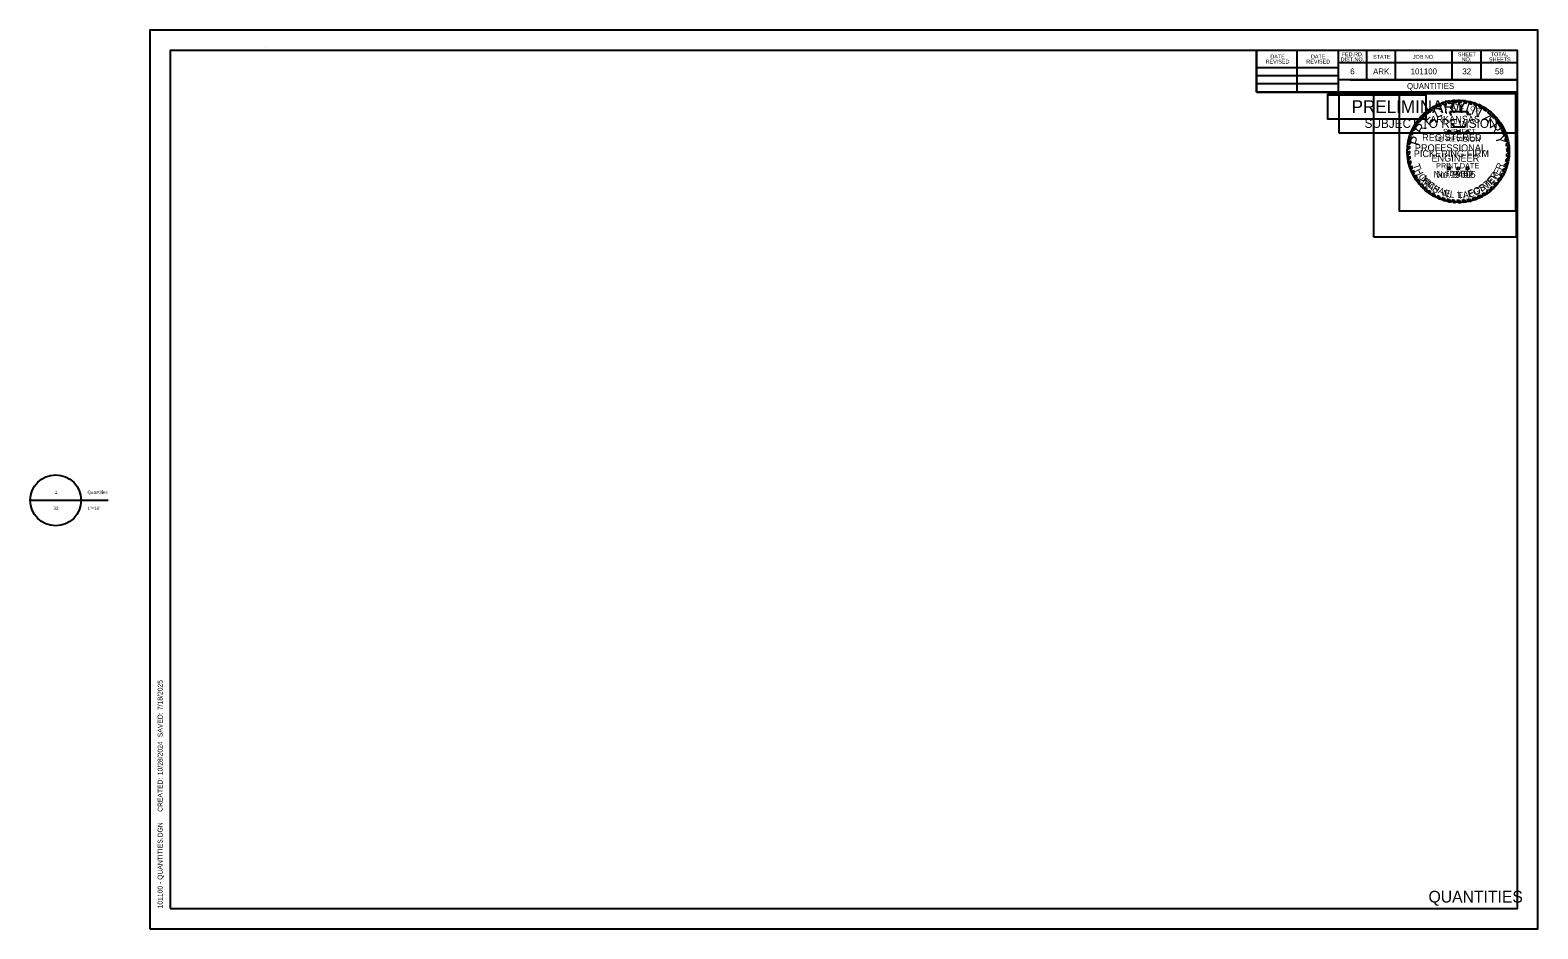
# Model space of a CAD drawing. Extents: x -0.12 to 1.42, y 0 to 0.92.
import ezdxf

# ---------------------------------------------------------------- set-up
doc = ezdxf.new("R2010")
doc.units = 0
for name, color, linetype in [('Default', 7, 'Continuous'), ('DSN_DRFT_Guideline-No-Plot', 7, 'Continuous'), ('SHET_Annotations', 7, 'Continuous'), ('SHET_Border-Lines', 7, 'Continuous'), ('SHET_Border-Text', 7, 'Continuous'), ('SHET_Stamp-Prelim', 7, 'Continuous'), ('SHET_Stamp-Seal', 7, 'Continuous'), ('STAMP_PE DIG SIG', 7, 'Continuous'), ('STAMP_PE_BACKGROUND', 7, 'Continuous'), ('STAMP_PE_FOSTER', 7, 'Continuous'), ('STAMP_PE_SEAL-INFO', 7, 'Continuous'), ('STAMP_PE_TAEGTMEYER', 7, 'Continuous'), ('STAMP_PRELIMINARY', 7, 'Continuous')]:
    doc.layers.add(name, color=color, linetype=linetype)

msp = doc.modelspace()

# ---------------------------------------------------------------- linework, layer by layer
at = {"layer": 'Default'}
for p, q in [((-0.1223, 0.4371), (-0.0702, 0.4371)), ((-0.096, 0.4371), (-0.0428, 0.4371))]:
    msp.add_line(p, q, dxfattribs=at)
msp.add_circle((-0.0962, 0.4371), 0.026, dxfattribs=at)
at = {"layer": 'DSN_DRFT_Guideline-No-Plot'}
msp.add_lwpolyline([(0, 0), (1.4167, 0), (1.4167, 0.9167), (0, 0.9167)], close=True, dxfattribs=at)
at = {"layer": 'SHET_Border-Lines'}
for p, q in [((0.1176, 0.8988), (0.1176, 0.8988)), ((0.1176, 0.8988), (0.1176, 0.8988)), ((1.1296, 0.8534), (1.1296, 0.8958)), ((1.1711, 0.8534), (1.1711, 0.8958)), ((1.2127, 0.8958), (1.2127, 0.8534)), ((1.2417, 0.8958), (1.2417, 0.866)), ((1.2712, 0.8958), (1.2712, 0.866)), ((1.3289, 0.8958), (1.3289, 0.866)), ((1.3584, 0.8958), (1.3584, 0.866)), ((1.1296, 0.8786), (1.2127, 0.8786)), ((1.3958, 0.8832), (1.2127, 0.8832)), ((1.3958, 0.8833), (1.3958, 0.8833)), ((1.1296, 0.8706), (1.2127, 0.8706)), ((1.1296, 0.8622), (1.2127, 0.8622)), ((1.3958, 0.866), (1.2127, 0.866)), ((1.2252, 0.866), (1.3958, 0.866)), ((1.3958, 0.8534), (1.1296, 0.8534))]:
    msp.add_line(p, q, dxfattribs=at)
for points in [[(0.0208, 0.0208), (1.3958, 0.0208), (1.3958, 0.8958), (0.0208, 0.8958)], [(1.1296, 0.8534), (1.3958, 0.8534), (1.3958, 0.8958), (1.1296, 0.8958)]]:
    msp.add_lwpolyline(points, close=True, dxfattribs=at)
at = {"layer": 'SHET_Stamp-Prelim'}
msp.add_lwpolyline([(1.2137, 0.8119), (1.3948, 0.8119), (1.3948, 0.8524), (1.2137, 0.8524)], close=True, dxfattribs=at)
at = {"layer": 'SHET_Stamp-Seal'}
msp.add_line((1.3219, 0.7895), (1.3219, 0.7895), dxfattribs=at)
msp.add_lwpolyline([(1.249, 0.7057), (1.3948, 0.7057), (1.3948, 0.8524), (1.249, 0.8524)], close=True, dxfattribs=at)
at = {"layer": 'STAMP_PE DIG SIG'}
msp.add_lwpolyline([(1.2022, 0.8508), (1.3022, 0.8508), (1.3022, 0.8258), (1.2022, 0.8258)], close=True, dxfattribs=at)
at = {"layer": 'STAMP_PE_BACKGROUND'}
for points in [[(1.2022, 0.8517), (1.3022, 0.8517), (1.3022, 0.8258), (1.2022, 0.8258)], [(1.3942, 0.8517), (1.275, 0.8517), (1.275, 0.7325), (1.3942, 0.7325)]]:
    msp.add_lwpolyline(points, close=True, dxfattribs=at)
at = {"layer": 'STAMP_PE_SEAL-INFO'}
for p, q in [((1.3002, 0.8313), (1.3028, 0.8306)), ((1.3021, 0.833), (1.3051, 0.8325)), ((1.3042, 0.8348), (1.3068, 0.8337)), ((1.3066, 0.8363), (1.309, 0.8352)), ((1.3087, 0.8377), (1.3112, 0.8365)), ((1.3112, 0.8391), (1.3138, 0.8378)), ((1.3137, 0.8403), (1.3158, 0.8387)), ((1.3165, 0.8415), (1.3181, 0.8397)), ((1.3184, 0.8422), (1.3206, 0.8405)), ((1.3217, 0.8432), (1.3233, 0.8413)), ((1.3239, 0.8438), (1.3259, 0.8418)), ((1.3266, 0.8443), (1.3283, 0.8422)), ((1.3269, 0.8337), (1.3456, 0.8337)), ((1.3276, 0.832), (1.3269, 0.8337)), ((1.3281, 0.8303), (1.3276, 0.832)), ((1.3295, 0.8447), (1.331, 0.8426)), ((1.3336, 0.8427), (1.3318, 0.8449)), ((1.3364, 0.8428), (1.3348, 0.845)), ((1.3389, 0.8426), (1.3375, 0.845)), ((1.3417, 0.8424), (1.3401, 0.8448)), ((1.3441, 0.842), (1.3427, 0.8445)), ((1.3456, 0.8337), (1.3443, 0.831)), ((1.3473, 0.8413), (1.3463, 0.8439)), ((1.3495, 0.8407), (1.3486, 0.8433)), ((1.352, 0.8399), (1.3512, 0.8426)), ((1.3544, 0.839), (1.3536, 0.8418)), ((1.357, 0.8379), (1.3564, 0.8406)), ((1.3594, 0.8366), (1.359, 0.8394)), ((1.3616, 0.8353), (1.3614, 0.8381)), ((1.364, 0.8337), (1.3639, 0.8366)), ((1.366, 0.8322), (1.3662, 0.8349)), ((1.3685, 0.8301), (1.3687, 0.8331)), ((1.3703, 0.8285), (1.3707, 0.8313)), ((1.2891, 0.8167), (1.2918, 0.8171)), ((1.2904, 0.8191), (1.2931, 0.8192)), ((1.2917, 0.8213), (1.2946, 0.8215)), ((1.293, 0.8232), (1.2959, 0.8232)), ((1.2946, 0.8253), (1.2977, 0.8254)), ((1.2965, 0.8276), (1.2994, 0.8274)), ((1.2983, 0.8295), (1.3014, 0.8293)), ((1.3282, 0.8297), (1.3281, 0.8303)), ((1.3293, 0.8201), (1.3291, 0.8213)), ((1.331, 0.8201), (1.3293, 0.8201)), ((1.331, 0.8177), (1.331, 0.8201)), ((1.3423, 0.8177), (1.331, 0.8177)), ((1.3424, 0.8196), (1.3423, 0.8177)), ((1.3429, 0.8213), (1.3424, 0.8196)), ((1.3443, 0.831), (1.3478, 0.831)), ((1.3478, 0.831), (1.347, 0.8297)), ((1.3723, 0.8264), (1.3727, 0.8294)), ((1.3738, 0.8247), (1.3746, 0.8273)), ((1.3756, 0.8223), (1.3764, 0.8251)), ((1.3769, 0.8206), (1.3779, 0.8232)), ((1.3786, 0.8178), (1.3796, 0.8205)), ((1.3797, 0.8157), (1.381, 0.8182)), ((1.381, 0.813), (1.3823, 0.8157)), ((1.2862, 0.8008), (1.2838, 0.7996)), ((1.2867, 0.8034), (1.2841, 0.802)), ((1.2847, 0.8048), (1.2873, 0.8059)), ((1.2853, 0.8071), (1.2879, 0.808)), ((1.2862, 0.8099), (1.2889, 0.8106)), ((1.287, 0.8121), (1.2898, 0.8129)), ((1.288, 0.8145), (1.2908, 0.8151)), ((1.3252, 0.8129), (1.3241, 0.8137)), ((1.3241, 0.8137), (1.3255, 0.8137)), ((1.3248, 0.8116), (1.3252, 0.8129)), ((1.3259, 0.8124), (1.3248, 0.8116)), ((1.3255, 0.8137), (1.3259, 0.815)), ((1.3259, 0.815), (1.3264, 0.8137)), ((1.327, 0.8116), (1.3259, 0.8124)), ((1.3264, 0.8137), (1.3277, 0.8137)), ((1.3277, 0.8137), (1.3266, 0.8129)), ((1.3266, 0.8129), (1.327, 0.8116)), ((1.3347, 0.8129), (1.3336, 0.8137)), ((1.3336, 0.8137), (1.335, 0.8137)), ((1.3343, 0.8116), (1.3347, 0.8129)), ((1.3354, 0.8124), (1.3343, 0.8116)), ((1.335, 0.8137), (1.3354, 0.815)), ((1.3354, 0.815), (1.3358, 0.8137)), ((1.3365, 0.8116), (1.3354, 0.8124)), ((1.3358, 0.8137), (1.3372, 0.8137)), ((1.3372, 0.8137), (1.3361, 0.8129)), ((1.3361, 0.8129), (1.3365, 0.8116)), ((1.3442, 0.8129), (1.3431, 0.8137)), ((1.3431, 0.8137), (1.3445, 0.8137)), ((1.3438, 0.8116), (1.3442, 0.8129)), ((1.3449, 0.8124), (1.3438, 0.8116)), ((1.3445, 0.8137), (1.3449, 0.815)), ((1.3449, 0.815), (1.3453, 0.8137)), ((1.346, 0.8116), (1.3449, 0.8124)), ((1.3453, 0.8137), (1.3467, 0.8137)), ((1.3467, 0.8137), (1.3456, 0.8129)), ((1.3456, 0.8129), (1.346, 0.8116)), ((1.3818, 0.8112), (1.3832, 0.8136)), ((1.3829, 0.8081), (1.3844, 0.8107)), ((1.3835, 0.8061), (1.3851, 0.8086)), ((1.3842, 0.8029), (1.386, 0.8054)), ((1.3846, 0.8008), (1.3866, 0.8028)), ((1.2857, 0.796), (1.2834, 0.7946)), ((1.2856, 0.7933), (1.2834, 0.7914)), ((1.2859, 0.7984), (1.2835, 0.7968)), ((1.2857, 0.791), (1.2835, 0.7892)), ((1.2858, 0.7882), (1.2838, 0.7862)), ((1.2861, 0.7858), (1.2842, 0.7837)), ((1.3846, 0.7855), (1.3871, 0.7867)), ((1.3849, 0.7876), (1.3874, 0.7891)), ((1.385, 0.798), (1.387, 0.7998)), ((1.3851, 0.7956), (1.3873, 0.7973)), ((1.3852, 0.7927), (1.3875, 0.7945)), ((1.3852, 0.7905), (1.3875, 0.792)), ((1.2866, 0.7833), (1.2847, 0.7812)), ((1.2871, 0.7809), (1.2854, 0.7786)), ((1.2878, 0.7784), (1.2861, 0.7761)), ((1.2886, 0.7761), (1.287, 0.7738)), ((1.2895, 0.7737), (1.288, 0.7713)), ((1.2905, 0.7715), (1.2892, 0.769)), ((1.3252, 0.7754), (1.3241, 0.7763)), ((1.3241, 0.7763), (1.3255, 0.7763)), ((1.3248, 0.7741), (1.3252, 0.7754)), ((1.3259, 0.7749), (1.3248, 0.7741)), ((1.3255, 0.7763), (1.3259, 0.7776)), ((1.3259, 0.7776), (1.3264, 0.7763)), ((1.327, 0.7741), (1.3259, 0.7749)), ((1.3264, 0.7763), (1.3277, 0.7763)), ((1.3277, 0.7763), (1.3266, 0.7754)), ((1.3266, 0.7754), (1.327, 0.7741)), ((1.3347, 0.7754), (1.3336, 0.7763)), ((1.3336, 0.7763), (1.335, 0.7763)), ((1.3343, 0.7741), (1.3347, 0.7754)), ((1.3354, 0.7749), (1.3343, 0.7741)), ((1.335, 0.7763), (1.3354, 0.7776)), ((1.3354, 0.7776), (1.3358, 0.7763)), ((1.3365, 0.7741), (1.3354, 0.7749)), ((1.3358, 0.7763), (1.3372, 0.7763)), ((1.3372, 0.7763), (1.3361, 0.7754)), ((1.3361, 0.7754), (1.3365, 0.7741)), ((1.3442, 0.7754), (1.3431, 0.7763)), ((1.3431, 0.7763), (1.3445, 0.7763)), ((1.3438, 0.7741), (1.3442, 0.7754)), ((1.3449, 0.7749), (1.3438, 0.7741)), ((1.3445, 0.7763), (1.3449, 0.7776)), ((1.3449, 0.7776), (1.3453, 0.7763)), ((1.346, 0.7741), (1.3449, 0.7749)), ((1.3453, 0.7763), (1.3467, 0.7763)), ((1.3467, 0.7763), (1.3456, 0.7754)), ((1.3456, 0.7754), (1.346, 0.7741)), ((1.3799, 0.7705), (1.3826, 0.7709)), ((1.3808, 0.7724), (1.3835, 0.7729)), ((1.382, 0.7753), (1.3847, 0.776)), ((1.3827, 0.7774), (1.3855, 0.7785)), ((1.3835, 0.7802), (1.3862, 0.7813)), ((1.3841, 0.7827), (1.3867, 0.7838)), ((1.2918, 0.769), (1.2907, 0.7662)), ((1.2931, 0.7667), (1.2921, 0.7641)), ((1.2942, 0.765), (1.2936, 0.7619)), ((1.2958, 0.7628), (1.2952, 0.7598)), ((1.2975, 0.7607), (1.297, 0.7578)), ((1.2992, 0.7588), (1.2988, 0.7559)), ((1.301, 0.757), (1.3008, 0.754)), ((1.3029, 0.7552), (1.3029, 0.7523)), ((1.3679, 0.7553), (1.3706, 0.7545)), ((1.3702, 0.7573), (1.3727, 0.7566)), ((1.3716, 0.7588), (1.3743, 0.7583)), ((1.3738, 0.7612), (1.3763, 0.7608)), ((1.3755, 0.7634), (1.3783, 0.7634)), ((1.3774, 0.7662), (1.3801, 0.7661)), ((1.3783, 0.7677), (1.3811, 0.768)), ((1.3049, 0.7536), (1.305, 0.7507)), ((1.3068, 0.7522), (1.307, 0.7493)), ((1.3092, 0.7506), (1.3095, 0.7478)), ((1.3111, 0.7495), (1.3117, 0.7466)), ((1.3138, 0.7481), (1.3147, 0.7452)), ((1.3159, 0.7471), (1.3169, 0.7443)), ((1.3187, 0.7461), (1.3198, 0.7433)), ((1.321, 0.7453), (1.3222, 0.7426)), ((1.3238, 0.7445), (1.325, 0.7419)), ((1.326, 0.7441), (1.3274, 0.7415)), ((1.3288, 0.7436), (1.3302, 0.7411)), ((1.3313, 0.7433), (1.3328, 0.7409)), ((1.334, 0.7432), (1.3356, 0.7409)), ((1.3365, 0.7432), (1.3384, 0.741)), ((1.3394, 0.7433), (1.3412, 0.7412)), ((1.3419, 0.7436), (1.344, 0.7416)), ((1.3444, 0.744), (1.3465, 0.7421)), ((1.3471, 0.7446), (1.3492, 0.7427)), ((1.3497, 0.7453), (1.352, 0.7436)), ((1.3524, 0.7462), (1.3549, 0.7447)), ((1.3548, 0.7471), (1.3571, 0.7456)), ((1.3573, 0.7483), (1.36, 0.7471)), ((1.3596, 0.7494), (1.3619, 0.7481)), ((1.3619, 0.7508), (1.3644, 0.7497)), ((1.3639, 0.7521), (1.3663, 0.751)), ((1.3664, 0.754), (1.369, 0.7532))]:
    msp.add_line(p, q, dxfattribs=at)
for radius, start, end in [(0.0521, 129.7326, 132.5376), (0.0498, 127.5297, 130.9683), (0.0521, 123.6199, 126.5906), (0.0498, 121.9746, 125.11), (0.0521, 117.6544, 120.8099), (0.0498, 115.6869, 119.1583), (0.0521, 111.3124, 114.7026), (0.0498, 110.3086, 113.1659), (0.0521, 105.2339, 109.0352), (0.0498, 104.0352, 107.3615), (0.0521, 99.7525, 102.7765), (0.0498, 98.258, 101.0329), (0.0521, 93.9381, 96.5517), (0.0498, 92.1102, 95.0367), (0.0521, 87.7298, 90.6707), (0.0498, 85.9628, 88.9097), (0.0521, 81.9732, 84.8236), (0.0498, 79.9264, 82.696), (0.0521, 75.3125, 77.9426), (0.0498, 73.5575, 76.2314), (0.0521, 69.6061, 72.3058), (0.0498, 67.6248, 70.504), (0.0521, 63.1329, 66.2704), (0.0498, 61.1558, 64.3784), (0.0521, 56.9003, 60.0942), (0.0498, 54.9238, 58.2702), (0.0498, 48.3016, 52.0395), (0.0521, 50.3492, 53.7159), (0.0521, 44.3405, 47.3929), (0.0521, 152.864, 155.5189), (0.0521, 147.0072, 149.899), (0.0498, 151.0315, 153.573), (0.0521, 141.6056, 144.4486), (0.0498, 145.0197, 148.2104), (0.0498, 139.301, 142.5873), (0.0521, 135.4021, 138.3031), (0.0498, 133.1331, 136.2562), (0.0498, 42.2212, 45.5512), (0.0498, 36.135, 39.5311), (0.0521, 38.1247, 41.2316), (0.0498, 29.9032, 33.6645), (0.0521, 31.9614, 35.4294), (0.0498, 23.7732, 27.2211), (0.0521, 25.9391, 29.0125), (0.0521, 170.0003, 172.6878), (0.0521, 164.3068, 166.894), (0.0521, 158.4077, 161.0701), (0.0498, 167.9048, 170.9039), (0.0498, 162.4331, 165.0013), (0.0498, 156.3402, 159.2319), (0.0498, 17.6802, 21.4251), (0.0521, 19.9538, 23.3141), (0.0498, 11.5444, 15.2364), (0.0498, 5.7599, 9.0606), (0.0521, 13.8421, 17.4447), (0.0521, 7.5852, 10.8621), (0.0521, 175.7409, 178.2066), (0.0521, 181.7251, 184.1626), (0.0521, 187.4204, 190.1927), (0.0498, 179.6454, 182.2633), (0.0498, 173.73, 176.4734), (0.0498, 185.4539, 188.234), (0.0498, 348.0778, 351.3435), (0.0498, 353.8632, 357.1274), (0.0498, 359.7329, 3.0639), (0.0521, 349.8305, 353.0885), (0.0521, 1.7215, 4.7268), (0.0521, 355.7156, 358.9569), (0.0521, 193.0369, 195.9973), (0.0521, 198.8967, 201.6281), (0.0498, 191.2274, 193.9858), (0.0498, 196.9675, 199.8353), (0.0521, 204.5479, 207.4328), (0.0498, 202.7761, 205.4791), (0.0498, 329.5549, 333.2076), (0.0498, 335.6038, 339.1858), (0.0521, 331.4037, 334.9332), (0.0498, 341.777, 345.0925), (0.0521, 337.3837, 340.9933), (0.0521, 343.8925, 347.035), (0.0521, 210.8636, 213.6571), (0.0498, 208.7883, 211.7934), (0.0521, 216.6115, 219.491), (0.0498, 214.1838, 217.2747), (0.0521, 222.48, 225.3801), (0.0498, 220.3909, 223.3056), (0.0498, 226.2494, 229.2407), (0.0498, 310.7744, 314.3161), (0.0521, 312.4518, 315.6633), (0.0498, 316.6531, 320.3711), (0.0521, 318.2846, 321.8043), (0.0498, 323.5851, 327.4407), (0.0521, 325.4405, 328.9872), (0.0521, 228.3665, 231.348), (0.0498, 232.229, 234.9336), (0.0521, 234.295, 236.9452), (0.0498, 238.2223, 240.8353), (0.0521, 240.1977, 242.8613), (0.0498, 244.3204, 246.9486), (0.0521, 246.576, 249.1558), (0.0498, 250.3491, 253.1216), (0.0521, 252.5967, 255.3252), (0.0498, 256.505, 259.1192), (0.0521, 258.4433, 261.1398), (0.0498, 262.3783, 265.2012), (0.0521, 264.1978, 267.1009), (0.0498, 268.3215, 271.277), (0.0521, 270.2548, 273.3361), (0.0498, 274.6157, 277.4486), (0.0521, 276.4239, 279.4357), (0.0498, 280.3459, 283.5814), (0.0521, 282.3199, 285.3702), (0.0498, 286.6423, 289.9783), (0.0521, 288.5709, 291.9733), (0.0498, 292.8745, 296.1185), (0.0521, 294.6481, 298.2166), (0.0498, 299.0768, 302.1724), (0.0521, 300.621, 303.8703), (0.0498, 304.823, 308.5143), (0.0521, 306.3721, 310.208)]:
    msp.add_arc((1.3354, 0.793), radius, start, end, dxfattribs=at)
at = {"layer": 'STAMP_PRELIMINARY'}
msp.add_circle((1.3354, 0.793), 0.0521, dxfattribs=at)

# ---------------------------------------------------------------- texts
at = {"layer": 'Default'}
for s, p in [('1', (-0.0971, 0.4437)), ('Quantities', (-0.0637, 0.4437)), ('32', (-0.0984, 0.4273)), ('1"=10\'', (-0.0637, 0.4273))]:
    msp.add_text(s, height=0.00328, dxfattribs=at).set_placement(p)
at = {"layer": 'SHET_Annotations'}
for s, height, p in [('6', 0.006, (1.2252, 0.8716)), ('ARK.', 0.006, (1.2485, 0.8716)), ('101100', 0.006, (1.2869, 0.8716)), ('32', 0.006, (1.3396, 0.8716)), ('58', 0.006, (1.3729, 0.8717)), ('QUANTITIES', 0.006, (1.2831, 0.8567)), ('QUANTITIES', 0.012, (1.3051, 0.0268))]:
    msp.add_text(s, height=height, dxfattribs=at).set_placement(p)
at = {"layer": 'SHET_Border-Text'}
for s, p in [('FED.RD.', (1.2165, 0.8901)), ('SHEET', (1.335, 0.8901)), ('TOTAL', (1.3686, 0.8901)), ('REVISED', (1.1388, 0.8826)), ('DATE', (1.1436, 0.8878)), ('REVISED', (1.1804, 0.8826)), ('DATE', (1.1851, 0.8878)), ('DIST.NO.', (1.2154, 0.8849)), ('STATE', (1.2485, 0.8875)), ('JOB NO.', (1.2891, 0.8875)), ('NO.', (1.339, 0.8849)), ('SHEETS', (1.3668, 0.8849))]:
    msp.add_text(s, height=0.004, dxfattribs=at).set_placement(p)
for s, p in [('7/18/2025', (0.0129, 0.2231)), ('  SAVED: ', (0.0129, 0.1916)), ('10/28/2024', (0.0129, 0.1567)), ('     CREATED: ', (0.0129, 0.1097)), ('101100 - QUANTITIES.DGN', (0.0129, 0.0208))]:
    msp.add_text(s, height=0.005, rotation=90, dxfattribs=at).set_placement(p)
at = {"layer": 'SHET_Stamp-Prelim'}
for s, height, p in [('PRELIMINARY', 0.013, (1.2266, 0.8322)), ('SUBJECT TO REVISION', 0.009, (1.2398, 0.817))]:
    msp.add_text(s, height=height, dxfattribs=at).set_placement(p)
at = {"layer": 'STAMP_PE_FOSTER'}
msp.add_text('No. 9402', height=0.00698, dxfattribs=at).set_placement((1.313, 0.7661))
for s, rotation, p in [('R', 54.5031, (1.373, 0.764)), ('M', 308.339, (1.297, 0.7652)), ('I', 314.1842, (1.3014, 0.7599)), ('C', 319.8733, (1.3034, 0.7579)), ('H', 327.7235, (1.3086, 0.7538)), ('A', 335.7276, (1.3141, 0.7506)), ('E', 343.5779, (1.3204, 0.748)), ('F', 15.8691, (1.3468, 0.7469)), ('O', 23.719, (1.3526, 0.7487)), ('S', 31.7234, (1.3588, 0.7517)), ('T', 39.4194, (1.3641, 0.7552)), ('E', 46.9613, (1.3689, 0.7594)), ('L', 350.8115, (1.3263, 0.7464)), ('L', 1.2666, (1.3349, 0.7455)), ('.', 6.8035, (1.3408, 0.7459))]:
    msp.add_text(s, height=0.0067, rotation=rotation, dxfattribs=at).set_placement(p)
at = {"layer": 'STAMP_PE_SEAL-INFO'}
for s, rotation, p in [('S', 23.5541, (1.3164, 0.8327)), ('T', 16.311, (1.3216, 0.8347)), ('A', 9.0679, (1.3269, 0.8361)), ('T', 1.8248, (1.3325, 0.8369)), ('E', 355.2002, (1.3375, 0.8369)), ('O', 342.2506, (1.3472, 0.8354)), ('F', 335.0075, (1.3526, 0.8335))]:
    msp.add_text(s, height=0.00436, rotation=rotation, dxfattribs=at).set_placement(p)
for s, height, p in [('ARKANSAS', 0.00698, (1.3069, 0.8223)), ('PROFESSIONAL', 0.006983, (1.2911, 0.7932)), ('REGISTERED', 0.00698, (1.2986, 0.8038)), ('ENGINEER', 0.00698, (1.3081, 0.7826))]:
    msp.add_text(s, height=height, dxfattribs=at).set_placement(p)
at = {"layer": 'STAMP_PE_TAEGTMEYER'}
for s, rotation, p in [('T', 289.646, (1.289, 0.7791)), ('H', 296.7339, (1.291, 0.7736)), ('O', 303.7708, (1.2943, 0.7674)), ('Y', 53.9986, (1.3733, 0.7628)), ('E', 63.0984, (1.377, 0.768)), ('R', 69.57, (1.3798, 0.7735)), ('M', 314.2033, (1.298, 0.7621)), ('A', 321.0594, (1.3034, 0.7567)), ('S', 327.8239, (1.308, 0.7531)), ('G', 23.3052, (1.3522, 0.7475)), ('T', 31.466, (1.3583, 0.7503)), ('M', 39.3, (1.3633, 0.7533)), ('E', 46.8094, (1.3692, 0.7582)), ('N', 344.2727, (1.3186, 0.7474)), ('.', 350.6464, (1.3254, 0.7456)), ('T', 3.0061, (1.3347, 0.7445)), ('A', 8.9826, (1.3405, 0.7448)), ('E', 17.6836, (1.3463, 0.7457))]:
    msp.add_text(s, height=0.00698, rotation=rotation, dxfattribs=at).set_placement(p)
msp.add_text('No. 19605', height=0.00698, dxfattribs=at).set_placement((1.3101, 0.7661))
at = {"layer": 'STAMP_PRELIMINARY'}
for s, rotation, p in [('E', 42.3578, (1.3048, 0.8192)), ('L', 25.513, (1.3131, 0.8266)), ('I', 12.5248, (1.3217, 0.8309)), ('M', 3.1074, (1.3278, 0.8326)), ('I', 342.3164, (1.3416, 0.833)), ('N', 333.9382, (1.3478, 0.8315)), ('R', 56.2292, (1.2984, 0.8095)), ('A', 315.6579, (1.3591, 0.8257)), ('R', 301.3831, (1.3668, 0.8184)), ('P', 73.913, (1.2953, 0.7982)), ('Y', 283.2593, (1.3729, 0.8084))]:
    msp.add_text(s, height=0.0101, rotation=rotation, dxfattribs=at).set_placement(p)
for s, height, p in [('SUBJECT', 0.00536, (1.3198, 0.8106)), ('TO REVISION', 0.005363, (1.3105, 0.8028)), ('PICKERING FIRM', 0.006983, (1.29, 0.7872)), ('PRINT DATE', 0.00536, (1.3128, 0.7757)), ('$DATE$', 0.00536, (1.3222, 0.768))]:
    msp.add_text(s, height=height, dxfattribs=at).set_placement(p)

doc.saveas('drawing.dxf')
